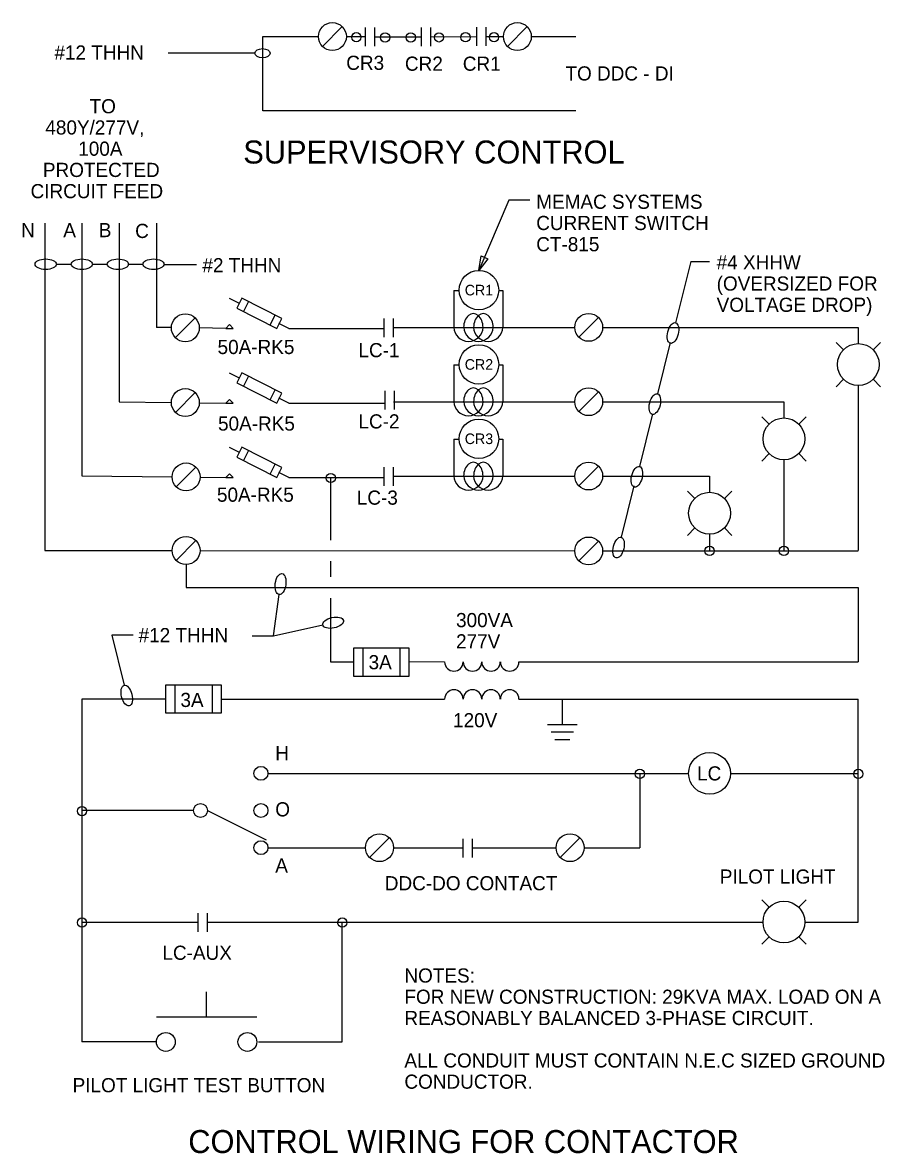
# Model space of a CAD drawing. Extents: x 10311 to 10362, y 10071 to 10187.
# Drawn here: x 10315.1 to 10355.7, y 10133.7 to 10187 of the extents above; entities that cross this region are included whole.
import ezdxf

# ---------------------------------------------------------------- set-up
doc = ezdxf.new("R2010")
doc.units = 0
for name, color, linetype in [('Default', 7, 'Continuous'), ('G-ANNO-TEXT', 7, 'Continuous'), ('G-DETL-LINE', 7, 'Continuous')]:
    doc.layers.add(name, color=color, linetype=linetype)

# ---------------------------------------------------------------- blocks, each defined once
blk = doc.blocks.new('E058')
at = {"layer": 'Default'}
blk.add_line((0.00086, -0.0021), (0.00507, 0.00212), dxfattribs=at)
blk.add_circle((0.00298, 0), 0.00298, dxfattribs=at)
blk = doc.blocks.new('e034')
at = {"layer": 'Default'}
for p, q in [((0.00794, 0.00397), (0.00794, 0.00794)), ((0, 0.00397), (0.01588, 0.00397))]:
    blk.add_line(p, q, dxfattribs=at)
for centre in [(0.00149, 0), (0.01439, 0)]:
    blk.add_circle(centre, 0.00149, dxfattribs=at)
blk = doc.blocks.new('E048')
at = {"layer": 'Default'}
for p, q in [((0, -0.0021), (0, 0.00186)), ((0.00198, -0.0021), (0.00198, 0.00186))]:
    blk.add_line(p, q, dxfattribs=at)
blk = doc.blocks.new('e071')
at = {"layer": 'Default'}
for p, q in [((0.01191, 0.00298), (0, 0.00298)), ((0, 0.00298), (0, -0.00298)), ((0.00198, 0.00298), (0.00198, -0.00298)), ((0.00992, 0.00298), (0.00992, -0.00298)), ((0.01191, -0.00298), (0.01191, 0.00298)), ((0, -0.00298), (0.01191, -0.00298))]:
    blk.add_line(p, q, dxfattribs=at)
blk = doc.blocks.new('e069')
at = {"layer": 'Default'}
for centre, start, end in [((-0.00595, 0), 180, 0), ((-0.00198, 0), 180, 0), ((0.00198, 0), 180, 0), ((0.00595, 0), 180, 0), ((-0.00595, -0.00794), 0, 180), ((-0.00198, -0.00794), 0, 180), ((0.00198, -0.00794), 0, 180), ((0.00595, -0.00794), 0, 180)]:
    blk.add_arc(centre, 0.00198, start, end, dxfattribs=at)
blk = doc.blocks.new('Fuse Switch')
at = {"layer": 'Default'}
for p, q in [((0.00154, 0.00212), (0.01003, 0.00645)), ((0.00861, 0.00573), (0.00969, 0.0036)), ((0.01003, 0.00645), (0.01111, 0.00432)), ((0.01059, 0.0053), (0.0127, 0.00635)), ((0.01111, 0.00432), (0.00262, 0)), ((0.00404, 0.00072), (0.00296, 0.00283)), ((0, 0), (0.00214, 0.00107)), ((0.00262, 0), (0.00154, 0.00212)), ((0.01191, 0), (0.0127, 0.00079)), ((0.01349, 0), (0.01191, 0)), ((0.0127, 0.00079), (0.01349, 0))]:
    blk.add_line(p, q, dxfattribs=at)
blk = doc.blocks.new('Power Ground')
at = {"layer": 'Default'}
for p, q in [((-0.00318, 0), (0.00318, 0)), ((0.00238, -0.00159), (-0.00238, -0.00159)), ((-0.00159, -0.00318), (0.00159, -0.00318))]:
    blk.add_line(p, q, dxfattribs=at)

msp = doc.modelspace()

# ---------------------------------------------------------------- linework, layer by layer
at = {"layer": 'Default'}
for p, q in [((10326.054, 10185.544), (10321.971, 10185.544)), ((10340.109, 10182.836), (10340.109, 10182.836))]:
    msp.add_line(p, q, dxfattribs=at)
msp.add_ellipse((10326.413, 10185.544), major_axis=(-0.359, 0), ratio=0.597027, dxfattribs=at)
at = {"layer": 'G-ANNO-TEXT'}
for p, q in [((10316.704, 10175.605), (10317.404, 10175.605)), ((10318.401, 10175.605), (10319.101, 10175.605)), ((10320.077, 10175.605), (10320.777, 10175.605)), ((10321.78, 10175.588), (10323.297, 10175.588)), ((10346.564, 10175.74), (10347.448, 10175.74)), ((10326.919, 10158.105), (10329.241, 10158.613))]:
    msp.add_line(p, q, dxfattribs=at)
for points in [[(10338.996, 10178.627), (10337.996, 10178.627), (10336.598, 10175.315)], [(10346.564, 10175.74), (10345.85, 10172.852)], [(10345.594, 10171.923), (10344.997, 10169.505)], [(10344.749, 10168.498), (10344.151, 10166.08)], [(10343.887, 10165.162), (10343.289, 10162.745)], [(10325.919, 10158.105), (10326.919, 10158.105), (10327.188, 10160.043)], [(10320.314, 10158.128), (10319.314, 10158.128), (10319.899, 10155.776)]]:
    msp.add_lwpolyline(points, dxfattribs=at)
msp.add_lwpolyline([(10337.011, 10175.865), (10336.598, 10175.315), (10336.704, 10175.994)], close=True, dxfattribs=at)
for centre, major_axis in [((10316.204, 10175.605), (-0.5, 0)), ((10317.904, 10175.605), (0.5, 0)), ((10319.601, 10175.605), (0.5, 0)), ((10321.277, 10175.605), (0.5, 0)), ((10345.73, 10172.366), (-0.12, -0.485)), ((10344.877, 10169.02), (-0.12, -0.485)), ((10344.031, 10165.595), (-0.12, -0.485)), ((10343.169, 10162.259), (-0.12, -0.485)), ((10327.257, 10160.538), (0.069, 0.495)), ((10329.73, 10158.72), (0.488, 0.107)), ((10320.019, 10155.29), (0.121, -0.485))]:
    msp.add_ellipse(centre, major_axis=major_axis, ratio=0.5, dxfattribs=at)
at = {"layer": 'G-DETL-LINE'}
for p, q in [((10331.246, 10186.756), (10331.246, 10185.881)), ((10331.684, 10186.756), (10331.684, 10185.881)), ((10333.872, 10186.756), (10333.872, 10185.881)), ((10334.309, 10186.756), (10334.309, 10185.881)), ((10336.487, 10186.766), (10336.487, 10185.891)), ((10336.925, 10186.766), (10336.925, 10185.891)), ((10330.355, 10186.328), (10331.246, 10186.328)), ((10331.684, 10186.319), (10333.872, 10186.319)), ((10334.309, 10186.319), (10336.487, 10186.328)), ((10336.925, 10186.328), (10337.748, 10186.328)), ((10339.061, 10186.328), (10341.15, 10186.328)), ((10316.161, 10177.537), (10316.161, 10162.128)), ((10317.912, 10177.537), (10317.912, 10165.646)), ((10319.662, 10177.537), (10319.662, 10169.13)), ((10321.413, 10177.537), (10321.413, 10172.631)), ((10335.422, 10174.37), (10335.422, 10172.626)), ((10335.422, 10174.37), (10335.669, 10174.37)), ((10337.527, 10174.37), (10337.72, 10174.37)), ((10337.72, 10174.37), (10337.72, 10172.626)), ((10322.119, 10172.621), (10321.413, 10172.631)), ((10324.679, 10172.585), (10323.432, 10172.603)), ((10327.655, 10172.585), (10332.135, 10172.585)), ((10332.572, 10172.631), (10341.106, 10172.631)), ((10342.419, 10172.631), (10354.454, 10172.631)), ((10354.454, 10172.631), (10354.454, 10171.865)), ((10353.409, 10171.925), (10353.758, 10171.577)), ((10355.15, 10171.577), (10355.498, 10171.925)), ((10335.422, 10170.869), (10335.669, 10170.869)), ((10335.422, 10170.869), (10335.422, 10169.125)), ((10337.527, 10170.869), (10337.72, 10170.869)), ((10337.72, 10170.869), (10337.72, 10169.125)), ((10353.409, 10169.836), (10353.758, 10170.184)), ((10355.15, 10170.184), (10355.498, 10169.836)), ((10354.454, 10169.896), (10354.454, 10162.128)), ((10319.662, 10169.13), (10322.119, 10169.099)), ((10323.432, 10169.083), (10324.679, 10169.067)), ((10332.572, 10169.13), (10341.106, 10169.13)), ((10342.419, 10169.13), (10350.953, 10169.13)), ((10350.953, 10169.13), (10350.953, 10168.364)), ((10327.655, 10169.067), (10332.181, 10169.067)), ((10349.908, 10168.424), (10350.256, 10168.076)), ((10351.649, 10168.076), (10351.997, 10168.424)), ((10335.422, 10167.368), (10335.669, 10167.368)), ((10335.422, 10167.368), (10335.422, 10165.624)), ((10337.527, 10167.368), (10337.72, 10167.368)), ((10337.72, 10167.368), (10337.72, 10165.624)), ((10349.908, 10166.335), (10350.256, 10166.683)), ((10351.649, 10166.683), (10351.997, 10166.335)), ((10350.953, 10166.395), (10350.953, 10162.128)), ((10317.912, 10165.646), (10322.156, 10165.596)), ((10323.469, 10165.581), (10324.679, 10165.566)), ((10327.655, 10165.566), (10332.135, 10165.566)), ((10329.605, 10165.566), (10329.605, 10162.613)), ((10332.572, 10165.629), (10341.106, 10165.629)), ((10342.419, 10165.629), (10347.452, 10165.629)), ((10347.452, 10165.629), (10347.452, 10164.863)), ((10346.407, 10164.923), (10346.755, 10164.575)), ((10348.148, 10164.575), (10348.496, 10164.923)), ((10346.407, 10162.834), (10346.755, 10163.182)), ((10347.452, 10162.894), (10347.452, 10162.128)), ((10348.148, 10163.182), (10348.496, 10162.834)), ((10316.161, 10162.128), (10322.156, 10162.121)), ((10323.469, 10162.12), (10341.106, 10162.1)), ((10342.419, 10162.1), (10354.454, 10162.1)), ((10322.812, 10161.464), (10322.812, 10160.378)), ((10329.605, 10161.613), (10329.605, 10160.878)), ((10322.812, 10160.378), (10354.454, 10160.378)), ((10354.454, 10160.378), (10354.454, 10156.877)), ((10329.605, 10159.878), (10329.605, 10156.877)), ((10329.605, 10156.877), (10330.689, 10156.877)), ((10333.314, 10156.893), (10334.979, 10156.877)), ((10338.48, 10156.877), (10354.454, 10156.877)), ((10317.912, 10155.126), (10317.912, 10138.975)), ((10321.85, 10155.126), (10317.912, 10155.126)), ((10324.476, 10155.126), (10334.979, 10155.126)), ((10338.48, 10155.126), (10354.454, 10155.126)), ((10340.526, 10153.923), (10340.526, 10155.126)), ((10354.454, 10144.623), (10354.454, 10155.126)), ((10326.664, 10151.625), (10346.467, 10151.625)), ((10344.169, 10151.625), (10344.169, 10148.124)), ((10348.436, 10151.625), (10354.454, 10151.625)), ((10323.163, 10149.874), (10317.912, 10149.874)), ((10323.82, 10149.874), (10326.587, 10148.49)), ((10326.664, 10148.124), (10331.259, 10148.124)), ((10332.572, 10148.124), (10335.854, 10148.124)), ((10336.292, 10148.124), (10340.231, 10148.124)), ((10341.544, 10148.124), (10344.169, 10148.124)), ((10349.908, 10145.667), (10350.256, 10145.319)), ((10351.649, 10145.319), (10351.997, 10145.667)), ((10317.912, 10144.623), (10323.382, 10144.623)), ((10323.82, 10144.623), (10349.968, 10144.623)), ((10330.165, 10138.975), (10330.165, 10144.623)), ((10351.937, 10144.623), (10354.454, 10144.623)), ((10349.908, 10143.579), (10350.256, 10143.927)), ((10351.649, 10143.927), (10351.997, 10143.579)), ((10321.413, 10138.975), (10317.912, 10138.975)), ((10326.227, 10138.975), (10330.165, 10138.975))]:
    msp.add_line(p, q, dxfattribs=at)
msp.add_lwpolyline([(10341.15, 10182.836), (10326.421, 10182.834), (10326.421, 10186.328), (10329.042, 10186.328)], dxfattribs=at)
for centre, radius in [((10330.825, 10186.298), 0.219), ((10332.181, 10186.288), 0.219), ((10333.387, 10186.288), 0.219), ((10334.716, 10186.29), 0.219), ((10335.963, 10186.295), 0.219), ((10337.306, 10186.298), 0.219), ((10336.598, 10174.386), 0.93), ((10336.598, 10170.885), 0.93), ((10354.454, 10170.881), 0.985), ((10336.598, 10167.384), 0.93), ((10350.953, 10167.38), 0.985), ((10329.621, 10165.536), 0.219), ((10347.452, 10163.879), 0.985), ((10347.452, 10162.102), 0.219), ((10350.953, 10162.102), 0.219), ((10347.452, 10151.625), 0.985), ((10326.336, 10151.625), 0.328), ((10344.169, 10151.599), 0.219), ((10354.454, 10151.599), 0.219), ((10317.912, 10149.849), 0.219), ((10323.491, 10149.874), 0.328), ((10326.336, 10149.874), 0.328), ((10326.336, 10148.124), 0.328), ((10350.953, 10144.623), 0.985), ((10317.912, 10144.597), 0.219), ((10330.165, 10144.597), 0.219)]:
    msp.add_circle(centre, radius, dxfattribs=at)
for centre, major_axis, ratio, start_param, end_param in [((10336.332, 10172.626), (0, 0.654), 0.7, 4.712389, 7.853982), ((10336.805, 10172.626), (0, 0.654), 0.7, 4.712389, 7.853982), ((10336.103, 10172.626), (0.687, 0), 0.952381, 3.141593, 6.283185), ((10336.576, 10172.626), (0.687, 0), 0.952381, 3.141593, 6.283185), ((10337.033, 10172.626), (0.687, 0), 0.952381, 3.141593, 6.283185), ((10336.332, 10169.125), (0, 0.654), 0.7, 4.712389, 7.853982), ((10336.805, 10169.125), (0, 0.654), 0.7, 4.712389, 7.853982), ((10336.103, 10169.125), (0.687, 0), 0.952381, 3.141593, 6.283185), ((10336.576, 10169.125), (0.687, 0), 0.952381, 3.141593, 6.283185), ((10337.033, 10169.125), (0.687, 0), 0.952381, 3.141593, 6.283185), ((10336.332, 10165.624), (0, 0.654), 0.7, 4.712389, 7.853982), ((10336.805, 10165.624), (0, 0.654), 0.7, 4.712389, 7.853982), ((10336.103, 10165.624), (0.687, 0), 0.952381, 3.141593, 6.283185), ((10336.576, 10165.624), (0.687, 0), 0.952381, 3.141593, 6.283185), ((10337.033, 10165.624), (0.687, 0), 0.952381, 3.141593, 6.283185)]:
    msp.add_ellipse(centre, major_axis=major_axis, ratio=ratio, start_param=start_param, end_param=end_param, dxfattribs=at)

# ---------------------------------------------------------------- block references
for name, p, xscale, yscale in [('E058', (10329.042, 10186.328), 220.53792472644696, 220.53792472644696), ('E058', (10337.748, 10186.328), 220.53792472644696, 220.53792472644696), ('E058', (10322.119, 10172.61), 220.53792472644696, 220.53792472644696), ('E048', (10332.135, 10172.631), 220.53792472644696, 220.53792472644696), ('E058', (10341.106, 10172.631), 220.53792472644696, 220.53792472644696), ('E058', (10322.119, 10169.091), 220.53792472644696, 220.53792472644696), ('E048', (10332.181, 10169.229), 220.53792472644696, 220.53792472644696), ('E058', (10341.106, 10169.13), 220.53792472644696, 220.53792472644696), ('E058', (10322.156, 10165.586), 220.53792472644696, 220.53792472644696), ('E048', (10332.135, 10165.629), 220.53792472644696, 220.53792472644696), ('E058', (10341.106, 10165.629), 220.53792472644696, 220.53792472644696), ('E058', (10322.156, 10162.121), 220.53792472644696, 220.53792472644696), ('E058', (10341.106, 10162.1), 220.53792472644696, 220.53792472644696), ('e071', (10330.689, 10156.86), 220.53792472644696, 220.53792472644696), ('e069', (10336.73, 10156.877), 220.53792472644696, 220.53792472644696), ('e071', (10321.85, 10155.126), 220.53792472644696, 220.53792472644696), ('Power Ground', (10340.526, 10153.923), 220.53792472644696, 220.53792472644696), ('E058', (10331.259, 10148.124), 220.53792472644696, 220.53792472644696), ('E048', (10335.854, 10148.124), 220.53792472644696, 220.53792472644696), ('E058', (10340.231, 10148.124), 220.53792472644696, 220.53792472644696), ('E048', (10323.382, 10144.623), 220.53792472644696, 220.53792472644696), ('e034', (10321.413, 10138.975), 297.72619838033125, 297.72619838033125)]:
    msp.add_blockref(name, p, dxfattribs=dict(at, xscale=xscale, yscale=yscale))
at = {"layer": 'G-DETL-LINE', "xscale": 220.53792472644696, "yscale": -220.53792472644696, "rotation": 180}
for p in [(10327.655, 10172.585), (10327.655, 10169.067), (10327.655, 10165.566)]:
    msp.add_blockref('Fuse Switch', p, dxfattribs=at)

# ---------------------------------------------------------------- texts
at = {"layer": 'Default'}
for s, height, p in [('CR3', 0.6667, (10330.35, 10184.759)), ('CR2', 0.6667, (10333.113, 10184.717)), ('CR1', 0.6667, (10335.837, 10184.716)), ('TO DDC - DI', 0.66667, (10340.669, 10184.258)), ('3A', 0.6667, (10331.402, 10156.528)), ('3A', 0.6667, (10322.545, 10154.751))]:
    msp.add_text(s, height=height, dxfattribs=at).set_placement(p)
at = {"layer": 'G-ANNO-TEXT'}
for s, height, p in [('#12 THHN', 0.6667, (10316.614, 10185.242)), ('TO', 0.6667, (10318.269, 10182.714)), ('480Y/277V,', 0.6667, (10316.187, 10181.714)), ('100A', 0.6667, (10317.735, 10180.714)), ('SUPERVISORY CONTROL', 1.08333, (10325.504, 10180.348)), ('PROTECTED', 0.6667, (10316.071, 10179.714)), ('CIRCUIT FEED', 0.66667, (10315.491, 10178.714)), ('MEMAC SYSTEMS', 0.66667, (10339.294, 10178.214)), ('CURRENT SWITCH', 0.66667, (10339.294, 10177.214)), ('N', 0.667, (10315.044, 10176.879)), ('A', 0.667, (10317.031, 10176.879)), ('B', 0.667, (10318.703, 10176.879)), ('C', 0.667, (10320.414, 10176.84)), ('CT-815', 0.6667, (10339.294, 10176.214)), ('#4 XHHW', 0.6667, (10347.786, 10175.362)), ('#2 THHN', 0.6667, (10323.58, 10175.226)), ('(OVERSIZED FOR', 0.66667, (10347.786, 10174.362)), ('CR1', 0.5, (10335.928, 10174.136)), ('VOLTAGE DROP)', 0.66667, (10347.786, 10173.362)), ('50A-RK5', 0.6667, (10324.294, 10171.374)), ('LC-1', 0.6667, (10330.925, 10171.225)), ('CR2', 0.5, (10335.928, 10170.635)), ('LC-2', 0.6667, (10330.925, 10167.869)), ('50A-RK5', 0.6667, (10324.315, 10167.768)), ('CR3', 0.5, (10335.928, 10167.134)), ('50A-RK5', 0.6667, (10324.264, 10164.418)), ('LC-3', 0.6667, (10330.847, 10164.279)), ('300VA', 0.6667, (10335.519, 10158.511)), ('#12 THHN', 0.6667, (10320.576, 10157.803)), ('277V', 0.6667, (10335.519, 10157.511)), ('120V', 0.6667, (10335.378, 10153.795)), ('H', 0.667, (10327.009, 10152.242)), ('LC', 0.6667, (10346.863, 10151.29)), ('O', 0.667, (10327.009, 10149.598)), ('A', 0.667, (10327.009, 10146.954)), ('DDC-DO CONTACT', 0.66667, (10332.166, 10146.118)), ('PILOT LIGHT', 0.66667, (10347.935, 10146.431)), ('LC-AUX', 0.6667, (10321.698, 10142.843)), ('NOTES:', 0.6667, (10333.088, 10141.771)), ('FOR NEW CONSTRUCTION: 29KVA MAX. LOAD ON A', 0.66667, (10333.088, 10140.771)), ('REASONABLY BALANCED 3-PHASE CIRCUIT.', 0.66667, (10333.088, 10139.771)), ('ALL CONDUIT MUST CONTAIN N.E.C SIZED GROUND', 0.66667, (10333.088, 10137.771)), ('PILOT LIGHT TEST BUTTON', 0.66667, (10317.47, 10136.606)), ('CONDUCTOR.', 0.6667, (10333.088, 10136.771)), ('CONTROL WIRING FOR CONTACTOR', 1.08333, (10322.915, 10133.742))]:
    msp.add_text(s, height=height, dxfattribs=at).set_placement(p)

doc.saveas('drawing.dxf')
